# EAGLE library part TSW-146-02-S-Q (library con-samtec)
THROUGH-HOLE .025" SQ POST HEADER Source: Samtec TSW.pdf
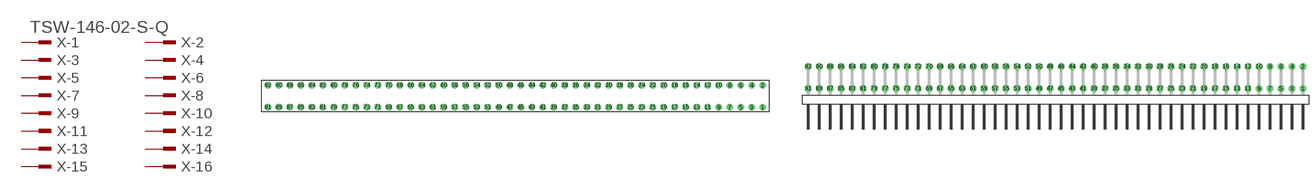
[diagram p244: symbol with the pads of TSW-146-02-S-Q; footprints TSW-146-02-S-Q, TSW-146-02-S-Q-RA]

Designator prefix X; gates -1=MPINV -2=MPIN -3=MPIN -4=MPIN -5=MPIN -6=MPIN -7=MPIN -8=MPIN -9=MPIN -10=MPIN -11=MPIN -12=MPIN -13=MPIN -14=MPIN -15=MPIN -16=MPIN -17=MPIN -18=MPIN -19=MPIN -20=MPIN -21=MPIN -22=MPIN -23=MPIN -24=MPIN -25=MPIN -26=MPIN -27=MPIN -28=MPIN -29=MPIN -30=MPIN -31=MPIN -32=MPIN -33=MPIN -34=MPIN -35=MPIN -36=MPIN -37=MPIN -38=MPIN -39=MPIN -40=MPIN -41=MPIN -42=MPIN -43=MPIN -44=MPIN -45=MPIN -46=MPIN -47=MPIN -48=MPIN -49=MPIN -50=MPIN -51=MPIN -52=MPIN -53=MPIN -54=MPIN -55=MPIN -56=MPIN -57=MPIN -58=MPIN -59=MPIN -60=MPIN -61=MPIN -62=MPIN -63=MPIN -64=MPIN -65=MPIN -66=MPIN -67=MPIN -68=MPIN -69=MPIN -70=MPIN -71=MPIN -72=MPIN -73=MPIN -74=MPIN -75=MPIN -76=MPIN -77=MPIN -78=MPIN -79=MPIN -80=MPIN -81=MPIN -82=MPIN -83=MPIN -84=MPIN -85=MPIN -86=MPIN -87=MPIN -88=MPIN -89=MPIN -90=MPIN -91=MPIN -92=MPIN

## TSW-146-02-S-Q (OC_FARNELL: unknown; OC_NEWARK: unknown)  [TSW-146-02-S-Q]
1  -1:1  pas
2  -2:1  pas
3  -3:1  pas
4  -4:1  pas
5  -5:1  pas
6  -6:1  pas
7  -7:1  pas
8  -8:1  pas
9  -9:1  pas
10  -10:1  pas
11  -11:1  pas
12  -12:1  pas
13  -13:1  pas
14  -14:1  pas
15  -15:1  pas
16  -16:1  pas
17  -17:1  pas
18  -18:1  pas
19  -19:1  pas
20  -20:1  pas
21  -21:1  pas
22  -22:1  pas
23  -23:1  pas
24  -24:1  pas
25  -25:1  pas
26  -26:1  pas
27  -27:1  pas
28  -28:1  pas
29  -29:1  pas
30  -30:1  pas
31  -31:1  pas
32  -32:1  pas
33  -33:1  pas
34  -34:1  pas
35  -35:1  pas
36  -36:1  pas
37  -37:1  pas
38  -38:1  pas
39  -39:1  pas
40  -40:1  pas
41  -41:1  pas
42  -42:1  pas
43  -43:1  pas
44  -44:1  pas
45  -45:1  pas
46  -46:1  pas
47  -47:1  pas
48  -48:1  pas
49  -49:1  pas
50  -50:1  pas
51  -51:1  pas
52  -52:1  pas
53  -53:1  pas
54  -54:1  pas
55  -55:1  pas
56  -56:1  pas
57  -57:1  pas
58  -58:1  pas
59  -59:1  pas
60  -60:1  pas
61  -61:1  pas
62  -62:1  pas
63  -63:1  pas
64  -64:1  pas
65  -65:1  pas
66  -66:1  pas
67  -67:1  pas
68  -68:1  pas
69  -69:1  pas
70  -70:1  pas
71  -71:1  pas
72  -72:1  pas
73  -73:1  pas
74  -74:1  pas
75  -75:1  pas
76  -76:1  pas
77  -77:1  pas
78  -78:1  pas
79  -79:1  pas
80  -80:1  pas
81  -81:1  pas
82  -82:1  pas
83  -83:1  pas
84  -84:1  pas
85  -85:1  pas
86  -86:1  pas
87  -87:1  pas
88  -88:1  pas
89  -89:1  pas
90  -90:1  pas
91  -91:1  pas
92  -92:1  pas

## TSW-146-02-S-Q-RA (OC_FARNELL: unknown; OC_NEWARK: unknown)  [TSW-146-02-S-Q-RA]
Pads as for TSW-146-02-S-Q

## Footprint TSW-146-02-S-Q (pad centres in mm)
THROUGH-HOLE .025" SQ POST HEADER Source: Samtec TSW.pdf
drill 1 pad 1.5 octagon: 1 57.15,-2.54; 2 57.15,2.54; 3 54.61,-2.54; 4 54.61,2.54; 5 52.07,-2.54; 6 52.07,2.54; 7 49.53,-2.54; 8 49.53,2.54; 9 46.99,-2.54; 10 46.99,2.54; 11 44.45,-2.54; 12 44.45,2.54; 13 41.91,-2.54; 14 41.91,2.54; 15 39.37,-2.54; 16 39.37,2.54; 17 36.83,-2.54; 18 36.83,2.54; 19 34.29,-2.54; 20 34.29,2.54; 21 31.75,-2.54; 22 31.75,2.54; 23 29.21,-2.54; 24 29.21,2.54; 25 26.67,-2.54; 26 26.67,2.54; 27 24.13,-2.54; 28 24.13,2.54; 29 21.59,-2.54; 30 21.59,2.54; 31 19.05,-2.54; 32 19.05,2.54; 33 16.51,-2.54; 34 16.51,2.54; 35 13.97,-2.54; 36 13.97,2.54; 37 11.43,-2.54; 38 11.43,2.54; 39 8.89,-2.54; 40 8.89,2.54; 41 6.35,-2.54; 42 6.35,2.54; 43 3.81,-2.54; 44 3.81,2.54; 45 1.27,-2.54; 46 1.27,2.54; 47 -1.27,-2.54; 48 -1.27,2.54; 49 -3.81,-2.54; 50 -3.81,2.54; 51 -6.35,-2.54; 52 -6.35,2.54; 53 -8.89,-2.54; 54 -8.89,2.54; 55 -11.43,-2.54; 56 -11.43,2.54; 57 -13.97,-2.54; 58 -13.97,2.54; 59 -16.51,-2.54; 60 -16.51,2.54; 61 -19.05,-2.54; 62 -19.05,2.54; 63 -21.59,-2.54; 64 -21.59,2.54; 65 -24.13,-2.54; 66 -24.13,2.54; 67 -26.67,-2.54; 68 -26.67,2.54; 69 -29.21,-2.54; 70 -29.21,2.54; 71 -31.75,-2.54; 72 -31.75,2.54; 73 -34.29,-2.54; 74 -34.29,2.54; 75 -36.83,-2.54; 76 -36.83,2.54; 77 -39.37,-2.54; 78 -39.37,2.54; 79 -41.91,-2.54; 80 -41.91,2.54; 81 -44.45,-2.54; 82 -44.45,2.54; 83 -46.99,-2.54; 84 -46.99,2.54; 85 -49.53,-2.54; 86 -49.53,2.54; 87 -52.07,-2.54; 88 -52.07,2.54; 89 -54.61,-2.54; 90 -54.61,2.54; 91 -57.15,-2.54; 92 -57.15,2.54

## Footprint TSW-146-02-S-Q-RA (pad centres in mm)
THROUGH-HOLE .025" SQ POST HEADER Source: Samtec TSW.pdf
drill 1 pad 1.5 octagon: 1 57.15,1.524; 2 57.15,6.604; 3 54.61,1.524; 4 54.61,6.604; 5 52.07,1.524; 6 52.07,6.604; 7 49.53,1.524; 8 49.53,6.604; 9 46.99,1.524; 10 46.99,6.604; 11 44.45,1.524; 12 44.45,6.604; 13 41.91,1.524; 14 41.91,6.604; 15 39.37,1.524; 16 39.37,6.604; 17 36.83,1.524; 18 36.83,6.604; 19 34.29,1.524; 20 34.29,6.604; 21 31.75,1.524; 22 31.75,6.604; 23 29.21,1.524; 24 29.21,6.604; 25 26.67,1.524; 26 26.67,6.604; 27 24.13,1.524; 28 24.13,6.604; 29 21.59,1.524; 30 21.59,6.604; 31 19.05,1.524; 32 19.05,6.604; 33 16.51,1.524; 34 16.51,6.604; 35 13.97,1.524; 36 13.97,6.604; 37 11.43,1.524; 38 11.43,6.604; 39 8.89,1.524; 40 8.89,6.604; 41 6.35,1.524; 42 6.35,6.604; 43 3.81,1.524; 44 3.81,6.604; 45 1.27,1.524; 46 1.27,6.604; 47 -1.27,1.524; 48 -1.27,6.604; 49 -3.81,1.524; 50 -3.81,6.604; 51 -6.35,1.524; 52 -6.35,6.604; 53 -8.89,1.524; 54 -8.89,6.604; 55 -11.43,1.524; 56 -11.43,6.604; 57 -13.97,1.524; 58 -13.97,6.604; 59 -16.51,1.524; 60 -16.51,6.604; 61 -19.05,1.524; 62 -19.05,6.604; 63 -21.59,1.524; 64 -21.59,6.604; 65 -24.13,1.524; 66 -24.13,6.604; 67 -26.67,1.524; 68 -26.67,6.604; 69 -29.21,1.524; 70 -29.21,6.604; 71 -31.75,1.524; 72 -31.75,6.604; 73 -34.29,1.524; 74 -34.29,6.604; 75 -36.83,1.524; 76 -36.83,6.604; 77 -39.37,1.524; 78 -39.37,6.604; 79 -41.91,1.524; 80 -41.91,6.604; 81 -44.45,1.524; 82 -44.45,6.604; 83 -46.99,1.524; 84 -46.99,6.604; 85 -49.53,1.524; 86 -49.53,6.604; 87 -52.07,1.524; 88 -52.07,6.604; 89 -54.61,1.524; 90 -54.61,6.604; 91 -57.15,1.524; 92 -57.15,6.604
